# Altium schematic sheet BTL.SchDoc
size A4; SheetNumber: 1; SheetTotal: 1
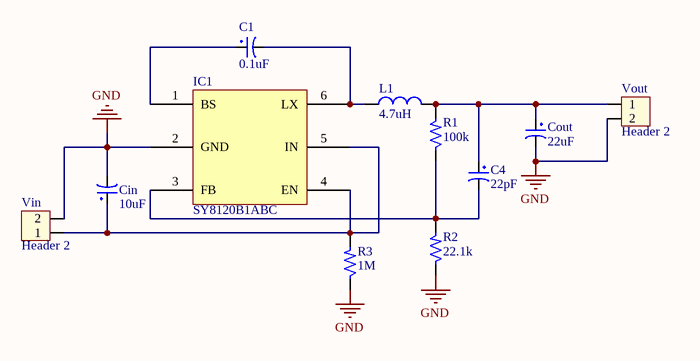
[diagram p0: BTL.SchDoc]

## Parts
C1  0.1uF  [tu hoa 5mm]
C4  22pF  [tu hoa 5mm]
Cin  10uF  [tu hoa 8mm]
Cout  22uF  [tu hoa 5mm]
IC1  SY8120B1ABC  [SY8120B1ABC_SOT23]
L1  4.7uH  [L/0.4]
R1  100k  [SM-RES-1206]
R2  22.1k  [SM-RES-1206]
R3  1M  [SM-RES-1206]
Vin  Header 2  [HED2]
Vout  Header 2  [HED2]

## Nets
GND: Cin.2 Cout.2 IC1.2(GND) R2.1 R3.1 Vin.2 Vout.2
NetC1_1: C1.1 IC1.1(BS)
NetC1_2: C1.2 IC1.6(LX) L1.1
NetC4_1: C4.1 Cout.1 L1.2 R1.2 Vout.1
NetC4_2: C4.2 IC1.3(FB) R1.1 R2.2
NetCin_1: Cin.1 IC1.4(EN) IC1.5(IN) R3.2 Vin.1

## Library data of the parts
C1 = Tu Hoa 0.1uF 50V 5x11: Cắm; Don_Vi: Con; So_Chan: 2; Ten_Linh_Kien: Tụ Hóa 0.1uF 50V; Ma_Hang: MH006853
C4 = Tu Hoa 2.2uF 100V 5x11: Cắm; Don_Vi: Con; So_Chan: 2; Ten_Linh_Kien: Tụ Hóa 2.2uF 100V; Ma_Hang: MH005081
Cin = Tu Hoa 4.7uF 400V 8x12: Cắm; Don_Vi: Con; So_Chan: 2; Ten_Linh_Kien: Tụ Hóa 4.7uF 400V 8x12MM; Ma_Hang: MH003744
Cout = Tu Hoa 22uF 25V 5x11: Cắm; So_Chan: 2; Don_Vi: Con; Ten_Linh_Kien: Tụ Hóa 22uF 25V; Ma_Hang: MH006858
IC1 = SY8120B1ABC: MF: Silergy
L1 = L1: Inductor; Value: 150 mH
R1-R3 = R: Resistor 1/4W; Value: R1/4W - 1K
Vin Vout = Hed2: Header 2 (Green)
